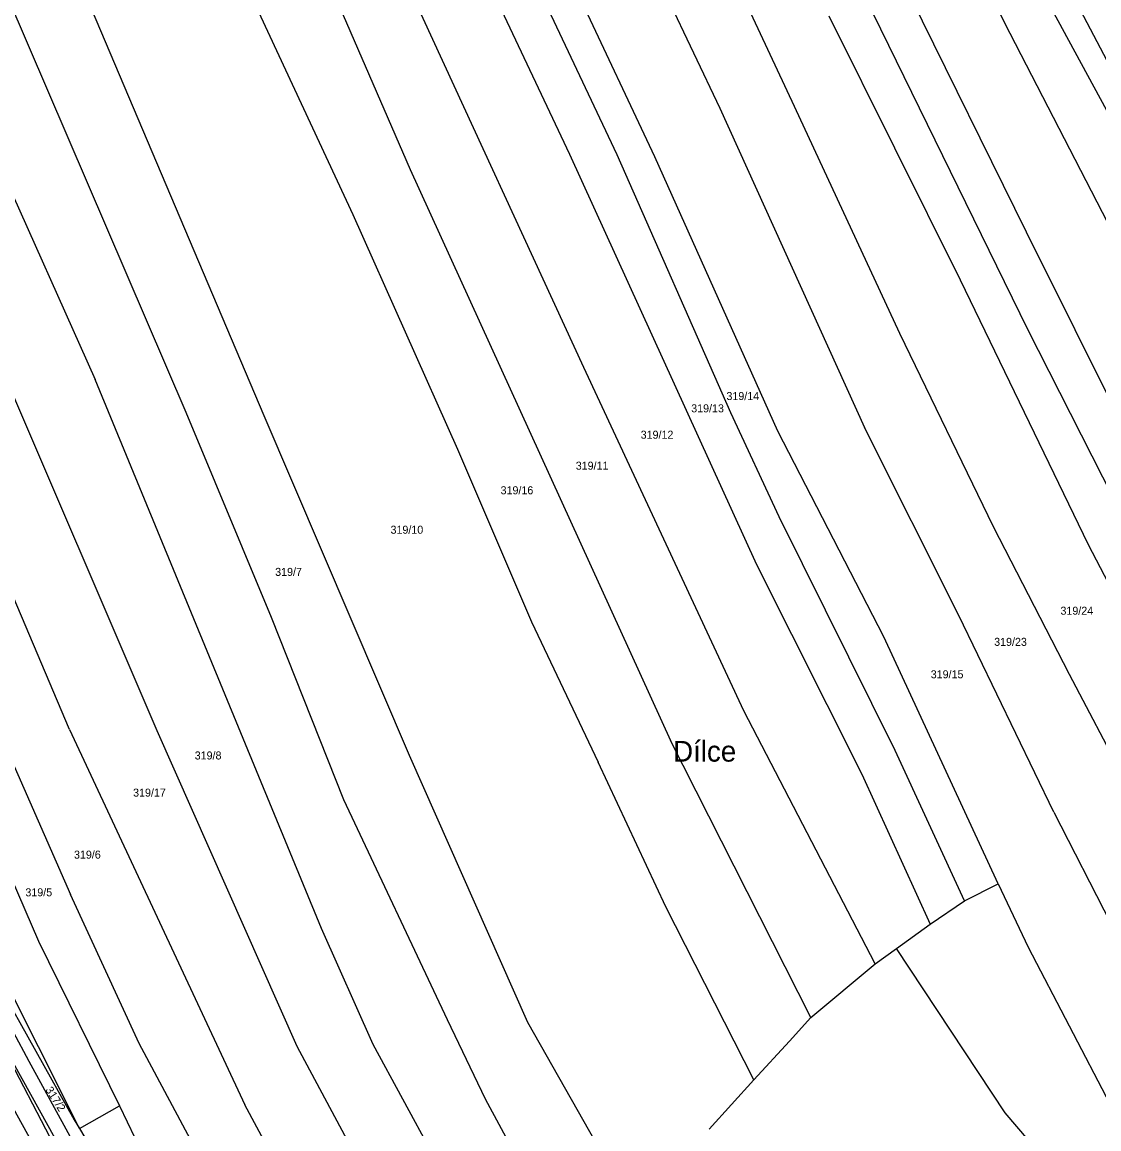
# Model space of a CAD drawing. Extents: x -762263 to -760336, y -1154405 to -1152076.
# Drawn here: x -761293.1 to -761064.3, y -1153124.6 to -1152889.5 of the extents above; entities that cross this region are included whole.
import ezdxf

# ---------------------------------------------------------------- set-up
doc = ezdxf.new("R2010")
doc.units = 0
for name, color, linetype in [('Vrstva 1', 7, 'Continuous'), ('Vrstva 15', 7, 'Continuous'), ('Vrstva 18', 7, 'Continuous'), ('Vrstva 4', 7, 'Continuous'), ('Vrstva 6', 7, 'Continuous')]:
    doc.layers.add(name, color=color, linetype=linetype)

msp = doc.modelspace()

# ---------------------------------------------------------------- linework, layer by layer
at = {"layer": 'Vrstva 1'}
for p, q in [((-761026.69, -1152966.14), (-761078.93, -1152866.43)), ((-761041.52, -1152947.17), (-761083.1, -1152870.5)), ((-761306.27, -1153082.93), (-761291.65, -1153110.16)), ((-761299.3, -1153091.79), (-761281.99, -1153122.63)), ((-761302.14, -1153097.65), (-761266.33, -1153166.38)), ((-761291.65, -1153110.16), (-761266.13, -1153156.64)), ((-761281.99, -1153122.63), (-761280.9, -1153124.46)), ((-761280.9, -1153124.46), (-761258.5, -1153162.06))]:
    msp.add_line(p, q, dxfattribs=at)
at = {"layer": 'Vrstva 4'}
for p, q in [((-761287.38, -1153133.79), (-761313.24, -1153087.23)), ((-761302.14, -1153097.65), (-761283.45, -1153131.38))]:
    msp.add_line(p, q, dxfattribs=at)
at = {"layer": 'Vrstva 6'}
for p, q in [((-761106.27, -1152845.61), (-761083.23, -1152891.86)), ((-761079.69, -1152934.08), (-761120.88, -1152850.57)), ((-761128.94, -1152853.67), (-761079.42, -1152954.68)), ((-761236.73, -1152860.53), (-761210.65, -1152920.78)), ((-761252.47, -1152866.67), (-761222.79, -1152930.35)), ((-761128.96, -1152907.44), (-761147.54, -1152867.61)), ((-761198.95, -1152870.62), (-761176.75, -1152917.54)), ((-761173.72, -1152962.87), (-761215.31, -1152872.6)), ((-761158.66, -1152918.1), (-761180.2, -1152872.25)), ((-761160.49, -1152874.87), (-761144.8, -1152907.76)), ((-761281.78, -1152878.6), (-761241.7, -1152973.06)), ((-761296.1, -1152884.3), (-761258.3, -1152972.37)), ((-761166.61, -1152917.72), (-761180.68, -1152888)), ((-761121.66, -1152888.19), (-761093.79, -1152944.26)), ((-761311.28, -1152890.04), (-761277.57, -1152965.41)), ((-761083.23, -1152891.86), (-761058.97, -1152938.85)), ((-761283.01, -1153039.72), (-761341.72, -1152901.52)), ((-761144.8, -1152907.76), (-761114.06, -1152975.57)), ((-761106.56, -1152955.67), (-761128.96, -1152907.44)), ((-761176.75, -1152917.54), (-761137.02, -1153004.67)), ((-761142.51, -1152972.45), (-761166.61, -1152917.72)), ((-761132.52, -1152976.41), (-761158.66, -1152918.1)), ((-761210.65, -1152920.78), (-761155.32, -1153042.05)), ((-761222.79, -1152930.35), (-761200.57, -1152980.22)), ((-761046.77, -1153000.14), (-761079.69, -1152934.08)), ((-761093.79, -1152944.26), (-761066.59, -1153000.45)), ((-761086.69, -1152996.72), (-761106.56, -1152955.67)), ((-761079.42, -1152954.68), (-761013.23, -1153085.4)), ((-761298.63, -1152960.34), (-761264.48, -1153039.93)), ((-761139.75, -1153035.76), (-761173.72, -1152962.87)), ((-761229.44, -1153082), (-761277.57, -1152965.41)), ((-761258.3, -1152972.37), (-761240.14, -1153015.86)), ((-761241.7, -1152973.06), (-761210.81, -1153045.19)), ((-761132.21, -1152994.6), (-761142.51, -1152972.45)), ((-761109.98, -1153020.06), (-761132.52, -1152976.41)), ((-761094.05, -1153015.51), (-761114.06, -1152975.57)), ((-761200.57, -1152980.22), (-761184.87, -1153016.9)), ((-761107.6, -1153044.23), (-761132.21, -1152994.6)), ((-761070.52, -1153028.09), (-761086.69, -1152996.72)), ((-761066.59, -1153000.45), (-761018.81, -1153092.03)), ((-761137.02, -1153004.67), (-761114.63, -1153049.23)), ((-761323.74, -1153006), (-761289.6, -1153084.69)), ((-761311.39, -1153009.87), (-761282.77, -1153074.76)), ((-761240.14, -1153015.86), (-761224.79, -1153054.63)), ((-761184.87, -1153016.9), (-761170.68, -1153046.65)), ((-761073.88, -1153057.27), (-761094.05, -1153015.51)), ((-761085.7, -1153072.54), (-761109.98, -1153020.06)), ((-761032.45, -1153100.64), (-761070.52, -1153028.09)), ((-761111.82, -1153089.51), (-761139.75, -1153035.76)), ((-761283.01, -1153039.72), (-761245.74, -1153119.44)), ((-761264.48, -1153039.93), (-761234.72, -1153106.98)), ((-761125.47, -1153100.93), (-761155.32, -1153042.05)), ((-761092.83, -1153076.15), (-761107.6, -1153044.23)), ((-761210.81, -1153045.19), (-761185.67, -1153101.92)), ((-761156.28, -1153077.37), (-761170.68, -1153046.65)), ((-761114.63, -1153049.23), (-761100.16, -1153081.09)), ((-761224.79, -1153054.63), (-761202.79, -1153101.31)), ((-761073.88, -1153057.27), (-761061.75, -1153080.91)), ((-761092.83, -1153076.15), (-761085.7, -1153072.54)), ((-761085.7, -1153072.54), (-761079.3, -1153085.97)), ((-761268.21, -1153106.39), (-761282.77, -1153074.76)), ((-761137.58, -1153114.14), (-761156.28, -1153077.37)), ((-761100.16, -1153081.09), (-761092.83, -1153076.15)), ((-761280.9, -1153124.46), (-761302.97, -1153080.6)), ((-761218.52, -1153106.64), (-761229.44, -1153082)), ((-761107.31, -1153086.24), (-761100.16, -1153081.09)), ((-761289.6, -1153084.69), (-761272.4, -1153119.63)), ((-761111.82, -1153089.51), (-761107.31, -1153086.24)), ((-761084.16, -1153121.16), (-761107.31, -1153086.24)), ((-761079.3, -1153085.97), (-761061.85, -1153119.38)), ((-761125.47, -1153100.93), (-761111.82, -1153089.51)), ((-761202.79, -1153101.31), (-761194.67, -1153118.18)), ((-761130.04, -1153105.92), (-761125.47, -1153100.93)), ((-761185.67, -1153101.92), (-761163.42, -1153141.18)), ((-761137.58, -1153114.14), (-761130.04, -1153105.92)), ((-761245.65, -1153148.53), (-761268.21, -1153106.39)), ((-761234.72, -1153106.98), (-761199.88, -1153172)), ((-761188.09, -1153162.54), (-761218.52, -1153106.64)), ((-761147.11, -1153124.64), (-761137.58, -1153114.14)), ((-761280.9, -1153124.46), (-761272.4, -1153119.63)), ((-761272.4, -1153119.63), (-761255.86, -1153153.87)), ((-761225.4, -1153157.19), (-761245.74, -1153119.44)), ((-761194.67, -1153118.18), (-761175.45, -1153153.62)), ((-761048.79, -1153162.61), (-761084.16, -1153121.16))]:
    msp.add_line(p, q, dxfattribs=at)

# ---------------------------------------------------------------- texts
at = {"layer": 'Vrstva 15'}
msp.add_text('Dílce', height=4.4, dxfattribs=at).set_placement((-761154.752, -1153046.56))
at = {"layer": 'Vrstva 18'}
for s, p in [('319/14', (-761143.423, -1152969.77)), ('319/13', (-761150.91, -1152972.38)), ('319/12', (-761161.647, -1152977.98)), ('319/11', (-761175.445, -1152984.56)), ('319/16', (-761191.413, -1152989.78)), ('319/10', (-761214.8, -1152998.16)), ('319/7', (-761239.312, -1153007.11)), ('319/24', (-761072.445, -1153015.36)), ('319/23', (-761086.532, -1153021.97)), ('319/15', (-761100.01, -1153028.86)), ('319/8', (-761256.412, -1153046.1)), ('319/17', (-761269.503, -1153053.99)), ('319/6', (-761282.062, -1153067.16)), ('319/5', (-761292.389, -1153075.16))]:
    msp.add_text(s, height=1.7, dxfattribs=at).set_placement(p)
msp.add_text('317/2', height=1.7, rotation=302.23524, dxfattribs=at).set_placement((-761288.21, -1153116.238))

doc.saveas('drawing.dxf')
